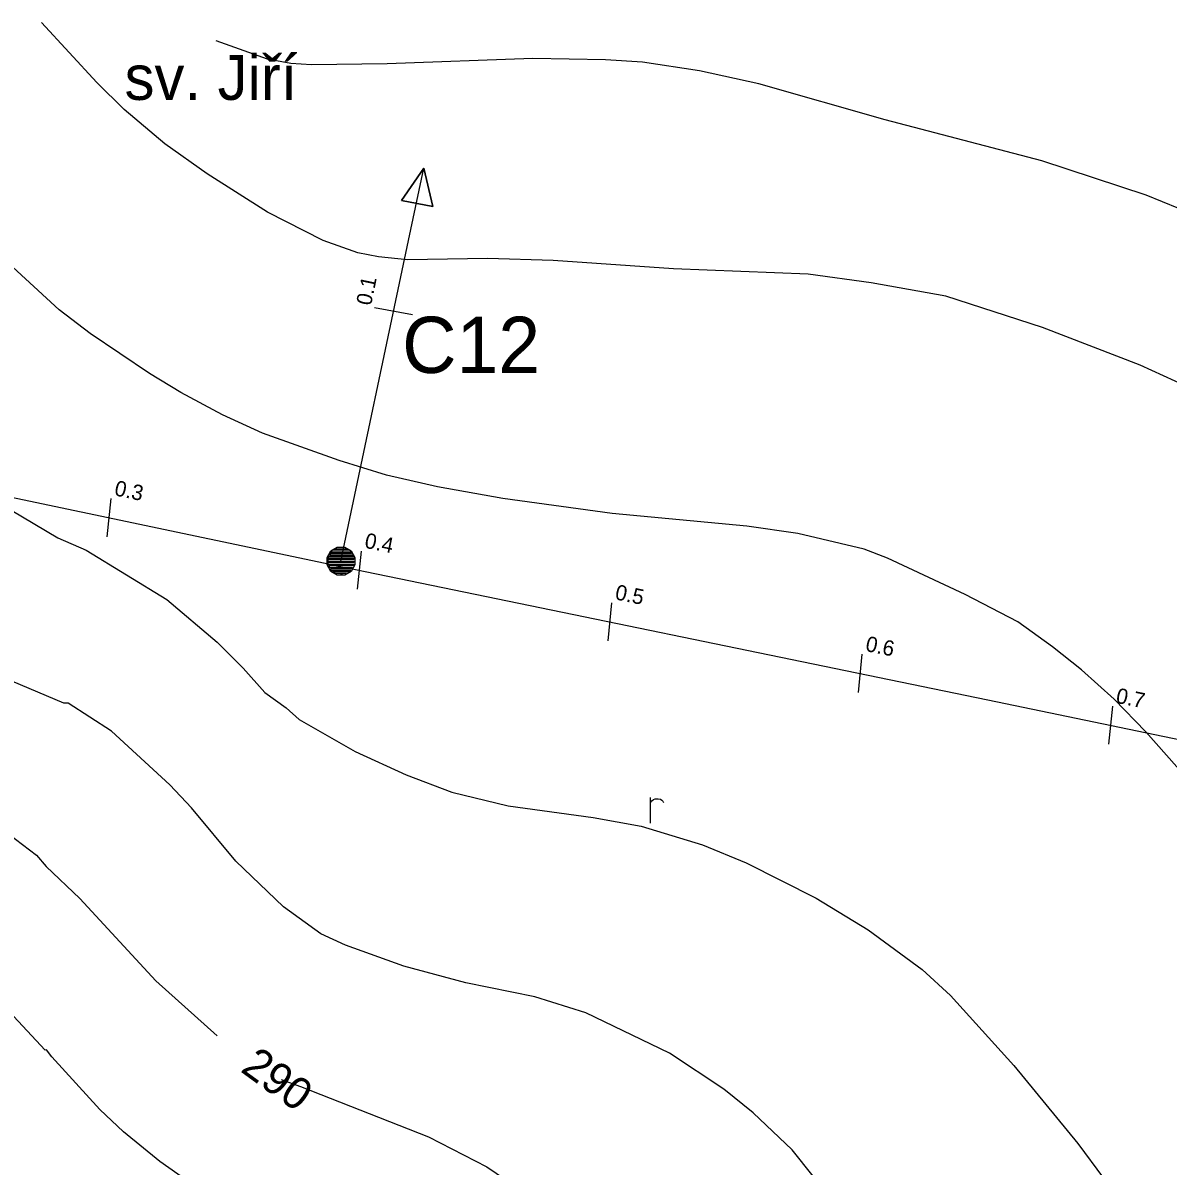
# Model space of a CAD drawing. Extents: x -645676 to -642474, y -1077513 to -1072613.
# Drawn here: x -643441.2 to -642993.3, y -1073932.9 to -1073485.7 of the extents above; entities that cross this region are included whole.
import ezdxf

# ---------------------------------------------------------------- set-up
doc = ezdxf.new("R2010")
doc.units = 0
for name, color, linetype in [('katastr_ln___zem____popis', 7, 'Continuous'), ('KULTURY_ZNACKY', 7, 'Continuous'), ('PC_NAVRH', 7, 'Continuous'), ('PC_POPIS_NAVRH', 7, 'Continuous'), ('PC_STAN_NAVRH', 7, 'Continuous'), ('VRSTEVNICE', 7, 'Continuous'), ('Vrstevnice_zd_razn_n____popis', 7, 'Continuous')]:
    doc.layers.add(name, color=color, linetype=linetype)

# ---------------------------------------------------------------- blocks, each defined once
blk = doc.blocks.new('$406')
blk.add_lwpolyline([(-0.19, 0.72), (0.2, 0.72), (0.54, 0.53), (0.73, 0.19), (0.73, -0.2), (0.54, -0.54), (0.2, -0.73), (-0.19, -0.73), (-0.53, -0.54), (-0.72, -0.2), (-0.72, 0.19), (-0.53, 0.53), (-0.2, 0.72), (-0.28, 0.64), (0.28, 0.64), (0.44, 0.56), (-0.44, 0.56), (-0.52, 0.48), (0.52, 0.48), (0.56, 0.4), (-0.55, 0.4), (-0.6, 0.32), (0.6, 0.32), (0.68, 0.24), (-0.59, 0.24), (-0.65, 0.24), (-0.68, 0.16), (0.59, 0.16), (0.68, 0.16), (0.68, 0.08), (-0.59, 0.08), (-0.68, 0.08), (-0.68, 0), (0.59, 0), (0.68, 0), (0.68, -0.08), (-0.59, -0.08), (-0.68, -0.08), (-0.68, -0.16), (0.59, -0.16), (0.68, -0.16), (0.65, -0.24), (-0.62, -0.24), (-0.65, -0.24), (-0.6, -0.32), (0.6, -0.32), (0.56, -0.4), (-0.55, -0.4), (-0.52, -0.48), (0.52, -0.48), (0.44, -0.56), (-0.44, -0.56), (-0.28, -0.64), (0.28, -0.64), (-0.02, -0.69)])
blk = doc.blocks.new('$944')
blk.add_line((0, 1.5), (0, -1.5))
blk = doc.blocks.new('$920')
for points in [[(0, 0), (-2.8, 1.25), (-2.8, -1.25), (0, 0)], [(-2.8, 1.25), (0, 0), (-2.8, -1.25), (-2.8, 1.25)]]:
    blk.add_lwpolyline(points)
blk = doc.blocks.new('$479')
for points in [[(0, 0), (0, 1.27), (0, 2)], [(0, 1.6), (0.1, 1.73), (0.23, 1.84), (0.37, 1.89), (0.6, 1.9), (0.77, 1.87), (0.87, 1.8), (0.96, 1.7), (1, 1.6)]]:
    blk.add_lwpolyline(points)

msp = doc.modelspace()

# ---------------------------------------------------------------- linework, layer by layer
at = {"layer": 'PC_NAVRH'}
for points in [[(-643316.83, -1073696.21), (-643290.45, -1073570.75), (-643284.37, -1073542.52)], [(-643651.3, -1073746.65), (-643642.16, -1073747.03), (-643634.9, -1073748.9), (-643627.26, -1073738.26), (-643603.35, -1073720.23), (-643590.34, -1073707.33), (-643581.82, -1073694.43), (-643570.81, -1073681.9), (-643563.42, -1073670.01), (-643558.29, -1073648.59), (-643471.17, -1073665.87), (-643315.58, -1073698.56), (-643063.81, -1073750.46), (-642778.16, -1073809.87)]]:
    msp.add_lwpolyline(points, dxfattribs=at)
at = {"layer": 'VRSTEVNICE'}
for points in [[(-642976.9, -1073632.16), (-643004.24, -1073619.63), (-643042.41, -1073604.81), (-643080.29, -1073592.57), (-643109.5, -1073587.41), (-643134.13, -1073584.02), (-643186.82, -1073581.89), (-643233.82, -1073578.61), (-643259.46, -1073577.9), (-643290.79, -1073578.33), (-643302.19, -1073577.19), (-643310.16, -1073575.62), (-643323.83, -1073570.78), (-643345.48, -1073559.67), (-643369.12, -1073544.71), (-643385.64, -1073533.03), (-643401.6, -1073519.5), (-643412.28, -1073508.97), (-643433.93, -1073485.47)], [(-642976.33, -1073563.51), (-643001.96, -1073553.12), (-643042.69, -1073539.59), (-643103.94, -1073523.64), (-643153.38, -1073509.54), (-643176.57, -1073504.41), (-643198.85, -1073501.06), (-643213.31, -1073500.14), (-643241.8, -1073499.57), (-643298.77, -1073501.7), (-643328.39, -1073502.13), (-643336.37, -1073501.56), (-643345.48, -1073499.85), (-643365.56, -1073492.73)], [(-642974.76, -1073793.81), (-643002.1, -1073763.04), (-643014.49, -1073750.23), (-643027.17, -1073738.83), (-643038.56, -1073729.72), (-643052.09, -1073720.03), (-643072.74, -1073709.35), (-643103.08, -1073695.11), (-643112.2, -1073691.55), (-643138.12, -1073685.43), (-643158.06, -1073682.58), (-643210.75, -1073677.59), (-643253.48, -1073671.75), (-643279.11, -1073667.2), (-643299.05, -1073662.64), (-643317.57, -1073656.94), (-643347.48, -1073646.12), (-643363.14, -1073639), (-643379.38, -1073630.31), (-643391.63, -1073622.9), (-643414.84, -1073607.24), (-643426.95, -1073597.98), (-643450.16, -1073576.62)], [(-643455.29, -1073670.76), (-643427.52, -1073687.14), (-643416.41, -1073691.98), (-643384.93, -1073711.2), (-643365.28, -1073728.01), (-643355.02, -1073738.12), (-643346.62, -1073747.66), (-643338.22, -1073753.65), (-643333.09, -1073758.2), (-643311.3, -1073770.74), (-643291.36, -1073779.85), (-643273.42, -1073786.69), (-643251.48, -1073791.96), (-643218.16, -1073796.51), (-643199.36, -1073799.93), (-643175.43, -1073807.2), (-643158.34, -1073814.32), (-643131, -1073828.13), (-643110.65, -1073840.44), (-643089.55, -1073856.05), (-643078.44, -1073866.16), (-643053.66, -1073893.5), (-643028.59, -1073924.12), (-643018.62, -1073937.65)], [(-643571.57, -1073679.89), (-643568.68, -1073690.49), (-643567.95, -1073693.86), (-643563.81, -1073707.22), (-643556.55, -1073723.45), (-643545.01, -1073739.4), (-643534.62, -1073749.8), (-643518.1, -1073760.91), (-643501.58, -1073770.74), (-643478.79, -1073781.99), (-643474.23, -1073785.41), (-643455.15, -1073796.66), (-643435.92, -1073811.33), (-643432.07, -1073815.74), (-643418.97, -1073828.27), (-643389.21, -1073860.46), (-643365.28, -1073881.97)], [(-643369.98, -1073943.49), (-643387.64, -1073931.1), (-643401.88, -1073919.57), (-643411.14, -1073910.74), (-643429.94, -1073890.23), (-643431.93, -1073887.38), (-643432.5, -1073887.52), (-643450.02, -1073868.72), (-643463.83, -1073856.05), (-643467.68, -1073853.63), (-643480.64, -1073843.23), (-643510.12, -1073824.29), (-643535.47, -1073811.04), (-643547.44, -1073802.64), (-643555.7, -1073795.95), (-643566.52, -1073785.83), (-643574.92, -1073776.72), (-643589.02, -1073757.06), (-643596, -1073744.25), (-643605.25, -1073712.36)], [(-643124.44, -1073946.48), (-643140.39, -1073926.54), (-643155.63, -1073912.02), (-643167.03, -1073902.76), (-643188.39, -1073888.8), (-643221.01, -1073872.99), (-643240.94, -1073866.73), (-643268, -1073861.17), (-643292.22, -1073854.76), (-643315, -1073846.5), (-643324.69, -1073842.09), (-643339.22, -1073831.55), (-643357.87, -1073813.61), (-643375.25, -1073792.81), (-643383.72, -1073783.73), (-643406.58, -1073762.76), (-643423.53, -1073751.79), (-643425.24, -1073751.79), (-643445.46, -1073743.25)], [(-643340.18, -1073899.06), (-643332.66, -1073901.76), (-643282.53, -1073921.42), (-643259.74, -1073933.24), (-643241.51, -1073945.63), (-643227.56, -1073957.45), (-643214.6, -1073969.56), (-643206.34, -1073979.38), (-643188.53, -1074008.86), (-643169.16, -1074047.6), (-643160.48, -1074062.13), (-643136.41, -1074097.74), (-643116.61, -1074123.66), (-643104.93, -1074137.75), (-643074.88, -1074170.51), (-643046.97, -1074205.12), (-643008.8, -1074260.67), (-642992.7, -1074282.03), (-642974.76, -1074302.96), (-642937.87, -1074341.56), (-642918.65, -1074359.93), (-642874.35, -1074397.96), (-642851.28, -1074420.6), (-642800.28, -1074483.73)]]:
    msp.add_lwpolyline(points, dxfattribs=at)

# ---------------------------------------------------------------- block references
at = {"layer": 'KULTURY_ZNACKY', "xscale": 5, "yscale": 5}
msp.add_blockref('$479', (-643195.72, -1073798.7), dxfattribs=at)
at = {"layer": 'PC_STAN_NAVRH'}
for name, p, xscale, yscale, rotation in [('$920', (-643284.37, -1073542.52), 5, 5.000000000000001, 79.194817), ('$944', (-643296.26, -1073598.35), 5, 5, 79.49212599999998), ('$944', (-643407.55, -1073679.24), 5.000000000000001, 5, -5.78902200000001), ('$944', (-643309.69, -1073699.77), 5.000000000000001, 5, -5.567502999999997), ('$944', (-643211.74, -1073719.96), 5.000000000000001, 5, -5.567502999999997), ('$944', (-643113.8, -1073740.15), 5.000000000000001, 5, -5.567502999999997), ('$944', (-643015.88, -1073760.42), 5.000000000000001, 5, -5.67241100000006)]:
    msp.add_blockref(name, p, dxfattribs=dict(at, xscale=xscale, yscale=yscale, rotation=rotation))
at = {"layer": 'PC_STAN_NAVRH', "xscale": 7.5, "yscale": 7.5}
msp.add_blockref('$406', (-643316.83, -1073696.21), dxfattribs=at)

# ---------------------------------------------------------------- texts
at = {"layer": 'katastr_ln___zem____popis'}
msp.add_text('sv. Jiří', height=17.5, dxfattribs=at).set_placement((-643401.44, -1073515.8))
at = {"layer": 'PC_POPIS_NAVRH'}
msp.add_text('C12', height=22, dxfattribs=at).set_placement((-643292.88, -1073622.63))
at = {"layer": 'PC_STAN_NAVRH'}
for s, rotation, p in [('0.1', 78.151, (-643305.07, -1073596.51)), ('0.3', 348.129, (-643405.71, -1073670.43)), ('0.4', 348.358, (-643307.88, -1073690.96)), ('0.5', 348.358, (-643209.93, -1073711.15)), ('0.6', 348.358, (-643111.99, -1073731.34)), ('0.7', 348.244, (-643014.05, -1073751.61))]:
    msp.add_text(s, height=6, rotation=rotation, dxfattribs=at).set_placement(p)
at = {"layer": 'Vrstevnice_zd_razn_n____popis'}
msp.add_text('290', height=12.5, rotation=324.018, dxfattribs=at).set_placement((-643356.51, -1073895.67))

doc.saveas('drawing.dxf')
